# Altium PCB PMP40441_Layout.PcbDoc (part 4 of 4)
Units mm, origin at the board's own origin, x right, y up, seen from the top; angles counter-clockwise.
Board outline 66.04 x 61.04 mm, 4 copper layers (Top Layer, Layer 2, Layer 3, Bottom Layer), stack 2.028 mm thick; 208 components, 122 nets, 788 pads, 545 vias.
Unrouted connection lines stored in the file: 24.
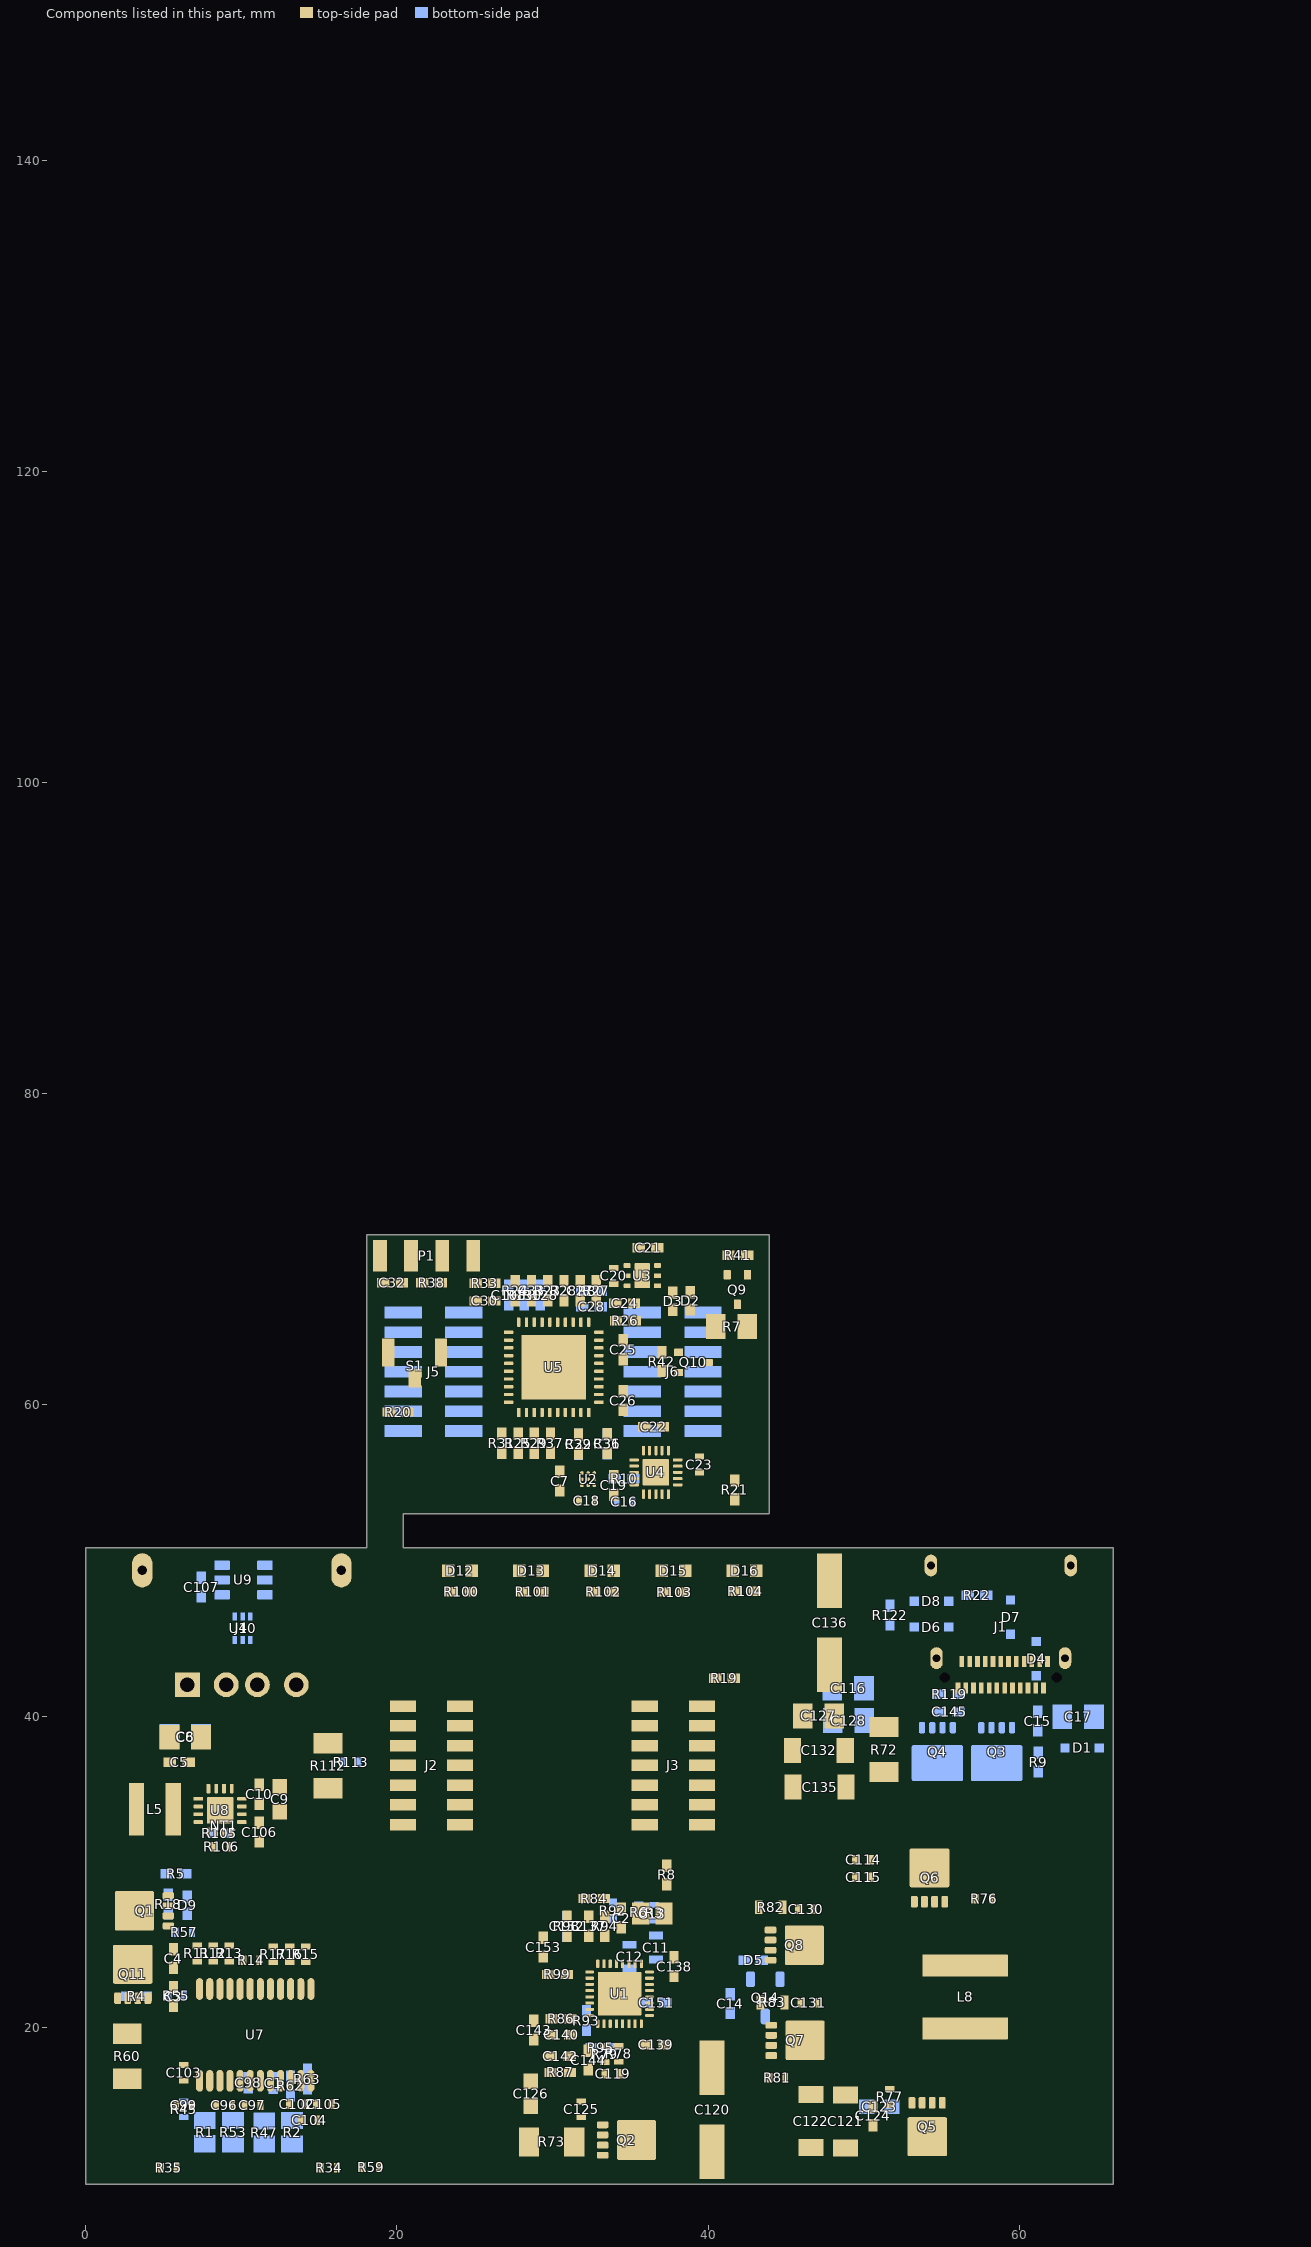
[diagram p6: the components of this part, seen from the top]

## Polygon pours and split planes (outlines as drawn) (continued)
CELL2 on Bottom Layer "Top Layer-No Net 9" (solid, remove dead copper, pour order 285): 10.947,11.379 10.719,11.151 10.719,10.719 10.871,10.566 12.275,10.566 12.3,10.566 12.453,10.719 12.453,11.201 12.275,11.379
NetR1_2 on Bottom Layer "Top Layer-No Net 9" (solid, remove dead copper, pour order 311): 13.513,11.379 13.284,11.151 13.284,10.719 13.437,10.566 14.84,10.566 14.866,10.566 15.018,10.719 15.018,11.201 14.84,11.379
CELL_N on Bottom Layer "Top Layer-No Net 9" (solid, remove dead copper, pour order 315): 6.071,11.405 5.842,11.176 5.842,10.744 5.994,10.592 7.398,10.592 7.423,10.592 7.576,10.744 7.576,11.227 7.398,11.405
VSYS on Bottom Layer "VSYS_L04_P220" (solid, remove dead copper, pour order 220): 2.565,34.468 1.295,34.468 1.092,34.265 1.092,33.934 1.321,33.706 2.591,33.706 2.769,33.884 2.769,34.265
VBAT- on Bottom Layer "Top Layer-No Net 10" (solid, remove dead copper, pour order 335): 3.327,18.034 4.877,18.034 5.105,17.805 5.105,13.437 5.105,10.82 4.496,10.211 0.838,10.211 0.279,10.77 0.279,17.678 0.635,18.034 1.905,18.034 2.134,17.805 2.134,17.526 2.337,17.323 2.616,17.323 2.87,17.323 3.023,17.475 3.023,17.729
VSYS on Bottom Layer "Bottom Layer-No Net 10" (solid, remove dead copper, pour order 269): 51.194,14.427 51.194,11.328 51.651,10.871 58.331,10.871 59.042,11.582 59.042,14.935 57.417,16.56 53.327,16.56
VSYS on Bottom Layer "Bottom Layer-No Net 11" (solid, remove dead copper, pour order 223): 41.407,13.131 41.407,10.972 41.56,10.82 41.966,10.82 42.169,11.023 42.169,13.157 42.093,13.233 41.509,13.233
VSYS on Bottom Layer "Bottom Layer-No Net 12" (solid, remove dead copper, pour order 278): 34.75,14.023 34.265,13.538 34.265,11.633 34.542,11.356 36.578,11.356 36.805,11.582 36.805,13.785 36.566,14.023
HB_SW1 on Bottom Layer "Bottom Layer-No Net 5" (solid, remove dead copper, pour order 242): 44.804,27.049 44.804,23.772 45.022,23.554 45.072,23.554 46.252,22.375 62.533,22.375 62.914,22.756 62.914,28.217 62.559,28.573 50.072,28.573 48.853,27.353 45.109,27.353
NetQ1_5 on Bottom Layer "NETQ1_5_L04_P327" (solid, remove dead copper, pour order 327): 0.965,25.273 0.965,23.443 1.472,22.936 3.734,22.936 4.278,23.481 4.278,24.652 3.658,25.273
NetQ1_5 on Bottom Layer "NETQ1_5_L04_P325" (solid, remove dead copper, pour order 325): 1.27,29.235 1.118,29.083 1.118,26.772 1.626,26.264 3.734,26.264 4.267,26.797 4.267,28.194 3.785,28.677 2.057,28.677 1.499,29.235
VO_A on Bottom Layer "VO_A_L04_P216" (solid, remove dead copper, pour order 216): 4.343,43.205 3.251,42.113 3.251,38.1 4.013,37.338 5.664,37.338 6.198,37.871 6.198,40.005 7.442,41.25 7.442,43.078 6.731,43.79 4.877,43.79
VSYS on Bottom Layer "VSYS_L04_P355" (solid, remove dead copper, pour order 355): 11.709,32.868 11.709,32.487 11.913,32.283 13.183,32.283 13.386,32.487 13.386,32.817 13.183,33.02 11.862,33.02
VBUS1 on Bottom Layer "VBUS1_L04_P363" (solid, remove dead copper, pour order 363): 52.832,38.735 55.245,38.735 55.372,38.862 55.372,41.783 55.245,41.91 54.864,41.91 53.467,43.307 49.911,43.307 49.276,42.672 49.276,38.608 49.911,37.973 52.07,37.973
VSBUS on Bottom Layer "VSBUS_L04_P365" (solid, remove dead copper, pour order 365): 60.198,38.1 60.452,37.846 60.452,35.941 60.325,35.814 53.086,35.814 52.832,36.068 52.832,37.846 53.086,38.1
CHG_ACN on Bottom Layer "CHG_ACN_L04_P377" (solid, remove dead copper, pour order 377): 50.546,37.592 52.451,37.592 52.578,37.465 52.578,35.814 52.832,35.56 62.865,35.56 63.246,35.179 63.246,29.464 62.738,28.956 50.292,28.956 50.038,29.21 50.165,29.337 50.165,37.211
VBUS on Bottom Layer "VBUS_L04_P379" (solid, remove dead copper, pour order 379): 57.531,38.735 59.055,38.735 59.182,38.862 59.182,39.624 59.309,39.751 61.468,39.751 61.976,39.243 61.976,37.846 62.357,37.465 63.627,37.465 63.881,37.719 63.881,40.64 63.119,41.402 57.404,41.402 57.15,41.148 57.15,39.116
PGND on Bottom Layer "PGND_L04_P391" (solid, remove dead copper, pour order 391): 1.524,50.546 64.77,50.546 65.913,49.403 65.913,10.668 65.405,10.16 0.762,10.16 0.254,10.668 0.254,49.276
NetC3_2 on Layer 2 "NETC3_2_L02_P345" (solid, remove dead copper, pour order 345): 0.61,21.666 0.279,21.336 0.279,19.38 0.483,19.177 0.94,19.177 1.118,19.355 1.118,21.463 0.914,21.666
AGND on Layer 2 "AGND_L02_P339" (solid, remove dead copper, pour order 339): 19.101,70.764 18.339,70.002 18.339,54.585 19.456,53.467 42.748,53.467 43.536,54.254 43.536,70.282 43.053,70.764
no net on Layer 2 "Top Layer-No Net 7" (solid, remove dead copper, shelved, pour order 291): 24.968,15.152 24.968,10.77 25.502,10.236 30.124,10.236 30.328,10.439 30.328,11.938 30.124,12.141 29.921,12.141 29.769,12.294 29.769,13.056 29.896,13.183 30.15,13.183 30.328,13.36 30.328,14.554 29.413,15.469 25.285,15.469
HB_SW1 on Layer 2 "Bottom Layer-No Net 5" (solid, remove dead copper, pour order 247): 44.754,27.026 44.754,23.749 44.972,23.531 45.023,23.531 46.202,22.352 62.483,22.352 62.864,22.733 62.864,28.194 62.509,28.55 50.022,28.55 48.803,27.33 45.059,27.33
VSYS on Layer 2 "Bottom Layer-No Net 10" (solid, remove dead copper, pour order 273): 52.092,13.839 52.092,11.354 52.727,10.719 57.705,10.719 58.113,11.126 58.113,13.973 57.887,14.199 52.451,14.199
VSYS on Layer 2 "Bottom Layer-No Net 12" (solid, remove dead copper, pour order 293): 34.788,14.131 34.23,13.572 34.23,11.895 34.661,11.464 36.203,11.464 36.627,11.887 36.627,13.614 36.111,14.131
VSYS on Layer 2 "Bottom Layer-No Net 11" (solid, remove dead copper, pour order 222): 41.377,13.132 41.377,10.973 41.529,10.82 41.935,10.82 42.139,11.024 42.139,13.157 42.062,13.233 41.478,13.233
VBAT+ on Layer 2 "VBAT+_L02_P295" (solid, remove dead copper, pour order 295): 23.571,14.376 22.911,13.716 22.911,11.608 23.343,11.176 29.439,11.176 29.693,11.43 29.693,11.824 29.439,12.078 29.286,12.078 29.134,12.23 29.134,13.043 29.261,13.17 29.515,13.17 29.693,13.348 29.693,13.945 29.261,14.376
VBAT- on Layer 2 "Top Layer-No Net 10" (solid, remove dead copper, pour order 299): 3.251,18.034 4.877,18.034 5.105,17.805 5.105,13.437 5.105,10.795 4.521,10.211 0.838,10.211 0.279,10.77 0.279,17.678 0.635,18.034 1.905,18.034 2.134,17.805 2.134,17.526 2.337,17.323 2.616,17.323 2.87,17.323 3.023,17.475 3.023,17.805
NetQ1_5 on Layer 2 "NETQ1_5_L02_P319" (solid, remove dead copper, pour order 319): 1.321,29.21 0.94,28.829 0.94,23.546 1.6,22.885 3.835,22.885 4.394,23.444 4.394,28.194 3.378,29.21
VSYS on Layer 2 "VSYS_L02_P232" (solid, remove dead copper, pour order 232): 11.913,32.283 13.183,32.283 13.386,32.487 13.386,32.817 13.157,33.045 11.887,33.045 11.709,32.868 11.709,32.487
VO_A on Layer 2 "VO_A_L02_P349" (solid, remove dead copper, pour order 349): 3.683,39.853 3.454,39.624 3.454,38.329 3.658,38.125 4.089,38.125 4.267,38.303 4.267,39.649 4.064,39.853
VBUS1 on Layer 2 "VBUS1_L02_P359" (solid, remove dead copper, pour order 359): 51.054,42.672 53.721,42.672 54.102,42.291 54.102,40.005 53.848,39.751 51.181,39.751 50.927,40.005 50.927,42.545
CHG_ACN on Layer 2 "CHG_ACN_L02_P373" (solid, remove dead copper, pour order 373): 50.546,37.592 52.451,37.592 52.578,37.465 52.578,35.814 52.832,35.56 62.865,35.56 63.246,35.179 63.246,29.464 62.738,28.956 50.292,28.956 50.038,29.21 50.165,29.337 50.165,37.211
VSBUS on Layer 2 "VSBUS_L02_P383" (solid, remove dead copper, pour order 383): 60.198,38.1 60.452,37.846 60.452,35.941 60.325,35.814 53.086,35.814 52.832,36.068 52.832,37.846 53.086,38.1
PGND on Layer 2 "PGND_L02_P387" (solid, remove dead copper, pour order 387): 1.524,50.546 64.77,50.546 65.913,49.403 65.913,10.668 65.405,10.16 0.762,10.16 0.254,10.668 0.254,49.276
NetC3_2 on Layer 3 "NETC3_2_L03_P351" (solid, remove dead copper, pour order 351): 0.61,21.666 0.279,21.336 0.279,19.38 0.483,19.177 0.94,19.177 1.118,19.355 1.118,21.463 0.914,21.666
AGND on Layer 3 "AGND_L03_P343" (solid, remove dead copper, pour order 343): 19.101,70.764 18.339,70.002 18.339,54.585 19.456,53.467 42.748,53.467 43.536,54.254 43.536,70.282 43.053,70.764
HB_SW1 on Layer 3 "Bottom Layer-No Net 5" (solid, remove dead copper, pour order 237): 44.82,26.67 44.82,23.735 45.378,23.176 46.202,22.352 62.509,22.352 62.916,22.758 62.916,28.219 62.56,28.575 60.122,28.575 59.055,27.508 54.292,27.508 53.96,27.176 53.323,26.539 52.469,26.539 52.033,26.975 45.124,26.975
VBAT+ on Layer 3 "Top Layer-No Net 7" (solid, remove dead copper, pour order 246): 24.968,14.116 24.968,10.77 25.502,10.236 29.425,10.236 29.566,10.377 29.566,10.7 28.473,11.792 28.473,14.478 28.245,14.707 26.721,14.707 25.559,14.707
VSYS on Layer 3 "Bottom Layer-No Net 12" (solid, remove dead copper, pour order 303): 34.774,14.032 34.215,13.473 34.215,11.796 34.647,11.365 35.96,11.365 36.612,12.017 36.612,13.299 35.879,14.032
VSYS on Layer 3 "Bottom Layer-No Net 11" (solid, remove dead copper, pour order 301): 41.377,13.132 41.377,10.973 41.529,10.82 41.935,10.82 42.139,11.024 42.139,13.157 42.062,13.233 41.478,13.233
VSYS on Layer 3 "Bottom Layer-No Net 10" (solid, remove dead copper, pour order 268): 52.532,13.398 52.532,10.744 53.04,10.236 56.667,10.236 58.577,12.146 58.577,14.491 58.057,15.011 54.145,15.011
VSYS on Layer 3 "VSYS_L03_P226" (solid, remove dead copper, pour order 226): 13.214,33.045 13.417,32.842 13.417,32.461 13.24,32.283 11.792,32.283 11.589,32.487 11.589,32.893 11.741,33.045
NetQ1_5 on Layer 3 "NETQ1_5_L03_P309" (solid, remove dead copper, pour order 309): 0.965,25.146 0.965,23.444 1.499,22.911 3.683,22.911 4.293,23.52 4.293,24.613 3.632,25.273 1.092,25.273
NetQ1_5 on Layer 3 "NETQ1_5_L03_P313" (solid, remove dead copper, pour order 313): 1.092,28.931 1.092,26.69 1.569,26.213 3.632,26.213 4.254,26.834 4.254,28.131 3.327,29.058 1.219,29.058
VBAT+ on Layer 3 "VBAT+_L03_P323" (solid, remove dead copper, pour order 323): 23.19,13.995 22.733,13.538 22.733,11.608 23.165,11.176 24.638,11.176 24.968,11.506 24.968,13.691 24.663,13.995
VBAT- on Layer 3 "Top Layer-No Net 10" (solid, remove dead copper, pour order 337): 3.251,18.034 4.877,18.034 5.105,17.805 5.105,13.437 5.105,10.795 4.521,10.211 0.838,10.211 0.279,10.77 0.279,17.678 0.635,18.034 1.905,18.034 2.134,17.805 2.134,17.526 2.337,17.323 2.616,17.323 2.87,17.323 3.023,17.475 3.023,17.805
VO_A on Layer 3 "VO_A_L03_P357" (solid, remove dead copper, pour order 357): 3.708,39.802 3.454,39.548 3.454,38.354 3.658,38.151 4.089,38.151 4.216,38.278 4.216,39.7 4.115,39.802
GND_A on Layer 3 "GND_A_L03_P218" (solid, remove dead copper, pour order 218): 1.473,50.571 0.33,49.428 0.33,40.691 2.438,38.583 14.656,38.583 17.475,41.402 17.475,50.063 16.942,50.597
VBUS1 on Layer 3 "VBUS1_L03_P361" (solid, remove dead copper, pour order 361): 51.054,42.672 53.721,42.672 54.102,42.291 54.102,40.005 53.848,39.751 51.181,39.751 50.927,40.005 50.927,42.545
CHG_ACN on Layer 3 "CHG_ACN_L03_P375" (solid, remove dead copper, pour order 375): 50.546,37.592 52.451,37.592 52.578,37.465 52.578,35.814 52.832,35.56 62.865,35.56 63.246,35.179 63.246,29.464 62.738,28.956 50.292,28.956 50.038,29.21 50.165,29.337 50.165,37.211
VSBUS on Layer 3 "VSBUS_L03_P385" (solid, remove dead copper, pour order 385): 60.198,38.1 60.452,37.846 60.452,35.941 60.325,35.814 53.086,35.814 52.832,36.068 52.832,37.846 53.086,38.1
PGND on Layer 3 "PGND_L03_P389" (solid, remove dead copper, pour order 389): 1.524,50.546 64.77,50.546 65.913,49.403 65.913,10.668 65.405,10.16 0.762,10.16 0.254,10.668 0.254,49.276

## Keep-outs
Keep-Out Layer:
  lines w0.025: 66.04,10.922 66.04,51.816 ; 66.04,11.938 66.04,52.832 ; 0,9.906 66.04,9.906 66.04,50.8 20.396,50.8 20.396,53.01 43.942,53.01 43.942,70.942 18.059,70.942 18.059,50.8 0,50.8 0,9.906
  text ".Layer_Name" at 14.656,-21.806 h1.52

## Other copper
Top Layer:
  pour cut-out: 28.397,19.736 28.245,19.583 28.245,18.821 28.397,18.669 29.058,18.669 29.261,18.466 29.261,16.764 29.435,16.59 30.832,16.59 31.953,16.59 31.953,19.126 31.344,19.736
  pour cut-out: 29.159,25.146 28.931,24.917 28.931,23.266 29.286,22.911 30.226,22.911 30.531,23.216 30.531,24.613 29.997,25.146
  pour cut-out: 30.505,27.594 30.505,26.746 30.836,26.416 36.22,26.416 36.424,26.619 36.424,28.067 36.22,28.27 31.182,28.27
  text ".Layer_Name" at 14.656,-21.806 h1.52
Layer 2:
  pour cut-out: 29.591,19.05 29.591,18.694 29.743,18.542 30.15,18.542 30.302,18.694 30.302,19.05 30.124,19.228 29.769,19.228
  pour cut-out: 32.664,27.051 32.791,26.924 32.791,25.222 32.283,24.714 29.972,24.714 29.82,24.562 29.82,24.232 29.972,24.079 31.801,24.079 32.156,23.724 32.156,21.514 29.859,19.217 30.161,18.706 32.106,20.65 33.401,20.65 33.604,20.853 33.604,21.302 32.859,22.047 32.859,24.299 33.528,24.968 33.528,27.051 35.052,27.051 35.179,27.178 35.179,27.508 35.052,27.635 31.42,27.635 31.318,27.534 31.318,27.153 31.42,27.051
Layer 3:
  pour cut-out: 29.743,19.202 29.604,19.063 29.604,18.682 29.794,18.491 30.124,18.491 30.302,18.669 30.302,19.05 30.15,19.202
  pour cut-out: 29.997,24.765 29.858,24.625 29.858,24.244 30.048,24.054 30.378,24.054 30.556,24.232 30.556,24.613 30.404,24.765
  pour cut-out: 31.42,27.635 31.318,27.534 31.318,27.153 31.394,27.076 31.775,27.076 31.877,27.178 31.877,27.508 31.75,27.635
  pour cut-out: 34.696,27.635 34.595,27.534 34.595,27.153 34.671,27.076 35.052,27.076 35.154,27.178 35.154,27.508 35.027,27.635
  pour cut-out: 32.969,21.361 32.829,21.222 32.83,20.841 33.02,20.65 33.35,20.65 33.528,20.828 33.528,21.209 33.376,21.361
Bottom Layer:
  pour cut-out: 32.639,21.082 32.639,19.736 34.036,19.736 34.036,20.65 33.325,21.361 32.918,21.361
  pour cut-out: 33.35,19.075 33.172,18.898 33.172,18.339 33.325,18.186 34.138,18.186 34.29,18.339 34.29,18.948 34.162,19.076
  pour cut-out: 29.591,19.05 29.591,18.694 29.743,18.542 30.15,18.542 30.302,18.694 30.302,19.05 30.124,19.228 29.769,19.228
  pour cut-out: 29.997,24.765 29.858,24.625 29.858,24.244 30.048,24.054 30.378,24.054 30.556,24.232 30.556,24.613 30.404,24.765
  pour cut-out: 30.48,27.534 30.48,26.619 30.531,26.568 31.318,26.568 31.928,27.178 31.928,27.508 31.801,27.635 30.582,27.635
  pour cut-out: 34.696,27.635 34.595,27.534 34.595,27.153 34.671,27.076 35.052,27.076 35.154,27.178 35.154,27.508 35.027,27.635
  pour cut-out: 36.88,25.757 37.313,25.324 37.313,24.079 36.678,23.444 34.493,23.444 34.341,23.597 34.341,25.453 34.645,25.757
  text ".Layer_Name" at 14.656,-21.806 h1.52

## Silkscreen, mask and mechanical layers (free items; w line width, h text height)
Top Overlay:
  text "PMP40441" at 16.993,28.829 h1.52
  text "Rev.1.1" at 16.993,26.873 h1.02
  text "-" at 3.835,13.843 h1.52
  text "+" at 20.625,13.741 h1.52
  text "3" at 14.453,11.633 h0.76
  text "0" at 7.137,11.608 h0.76
  text "1" at 9.703,11.608 h0.76
  text "2" at 11.963,11.608 h0.76
  text ".Layer_Name" at 14.656,-21.806 h1.52
Bottom Overlay:
  text "PMP40442" at 27.229,55.093 h1.85
  text ".Layer_Name" at 14.656,-21.806 h1.52
Top Paste:
  region: 47.669,27.28 47.669,22.733 52.153,22.733 52.153,27.28
  text ".Layer_Name" at 14.656,-21.806 h1.52
Bottom Paste:
  text ".Layer_Name" at 14.656,-21.806 h1.52
Top Solder:
  region: 13.494,11.379 13.316,11.201 13.316,10.719 13.469,10.566 14.808,10.566 14.808,11.379
  region: 10.954,11.379 10.776,11.201 10.776,10.719 10.929,10.566 12.294,10.566 12.471,10.744 12.471,11.201 12.294,11.379
  region: 8.541,11.405 8.363,11.227 8.363,10.744 8.516,10.592 9.881,10.592 10.058,10.77 10.058,11.227 9.881,11.405
  region: 47.663,27.292 47.663,22.746 52.146,22.746 52.146,27.292
  region: 0.279,13.97 0.279,10.77 0.813,10.236 4.394,10.236 4.394,11.506 5.08,11.506 5.08,12.497 5.08,13.97
  region: 6.198,11.405 6.198,10.592 7.391,10.592 7.569,10.77 7.569,11.227 7.391,11.405
  region: 22.022,15.189 22.022,10.262 26.365,10.262 26.365,15.189
  region: 50.673,34.925 62.738,34.925 63.246,34.417 63.246,29.464 62.738,28.956 50.546,28.956 50.165,29.337 50.165,34.417
  text ".Layer_Name" at 14.656,-21.806 h1.52
  text ".Layer_Name" at 14.656,-21.806 h1.52
Bottom Solder:
  region: 5.055,17.069 0.33,17.069 0.33,10.719 0.762,10.287 4.521,10.287 5.055,10.82
  region: 36.779,13.679 36.779,11.569 36.581,11.371 34.527,11.371 34.239,11.659 34.239,13.487 34.79,14.038 36.551,14.038 36.779,13.809
  region: 35.23,20.632 35.23,23.292 32.842,23.292 32.842,21.946 34.156,20.632
  region: 58.177,28.393 59.117,27.454 59.752,27.454 60.59,28.292 62.724,28.292 62.724,22.602 46.283,22.602 44.969,23.915 44.969,27.123 45.227,27.381 48.971,27.381 49.983,28.393 52.696,28.393
  region: 59.03,14.91 59.03,11.659 58.268,10.897 51.74,10.897 51.232,11.405 51.232,13.97 52.756,13.97 52.756,14.681 54.61,16.535 57.404,16.535
  region: 50.673,34.925 62.738,34.925 63.246,34.417 63.246,29.464 62.738,28.956 50.546,28.956 50.165,29.337 50.165,34.417
  text ".Layer_Name" at 14.656,-21.806 h1.52
Drill Guide:
  text ".Layer_Name" at 14.656,-21.806 h1.52
M1 Board Outline:
  the board outline again, w0.051
  text ".Layer_Name" at 14.656,-21.806 h1.52
M2 Board Dimensions:
  rectangle: 3.175,-10.16 12.7,-6.985
  rectangle: 0,-6.985 3.175,-3.81
  lines w0.178: 0,-6.985 25.4,-6.985 ; 3.175,-10.16 3.175,-3.81 ; 6.35,-10.16 6.35,-3.81 ; 12.7,-10.16 12.7,-3.81 ; 19.05,-10.16 19.05,-3.81 ; 0,-10.16 0,-3.81 25.4,-3.81 25.4,-10.16 0,-10.16
  text ".Layer_Name" at 14.656,-21.806 h1.52
M3 3D STEP Top:
  text ".Layer_Name" at 14.656,-21.806 h1.52
M4 3D STEP Bottom:
  text ".Layer_Name" at 14.656,-21.806 h1.52
M5 Assembly Top:
  lines w0.254: -7.417,-23.626 160.223,-23.626 ; -7.417,-18.462 160.274,-18.462 ; -7.417,-13.297 -7.417,-28.791 94.31,-28.791 160.274,-28.791 160.274,-13.297 -7.404,-13.297 -7.404,-28.791 32.614,-28.791 ; 55.194,-28.791 55.194,-13.297 ; 87.376,-18.462 87.376,-13.297 ; 108.712,-18.462 108.712,-13.297 ; 124.511,-28.956 124.511,-23.804
  text "COMPONENTS MARKED 'DNP' SHOULD NOT BE POPULATED." at 29.299,-8.09 h1.52
  text "ASSEMBLY VARIANT:" at 29.286,-11.024 h1.52
  text ".VariantName" at 55.601,-11.024 h1.52
  text "PCB VIEWED FROM TOP SIDE" at -5.804,-16.654 h1.52
  text "BOARD #:" at 57.099,-16.654 h1.52
  text ".PRJ_Number" at 70.955,-16.654 h1.52
  text "REV:" at 92.405,-16.654 h1.52
  text ".PCB_Rev" at 99.809,-16.654 h1.52
  text "SVN REV:" at 113.69,-16.654 h1.52
  text ".VersionControl_RevNumber" at 126.543,-16.654 h1.52
  text "TID #:" at 57.099,-21.819 h1.52
  text ".TID" at 70.955,-21.819 h1.52
  text "PLOT NAME =" at -5.804,-27.034 h1.52
  text ".plot_File_Name" at 14.656,-27.034 h1.52
  text "GENERATED    :" at 57.15,-27.034 h1.52
  text ".Print_Date" at 79.235,-27.034 h1.52
  text ".Print_Time" at 97.752,-27.034 h1.52
  text "TEXAS INSTRUMENTS" at 129.87,-27.034 h1.52
M6 Assembly Bottom:
  lines w0.254: -7.429,-18.474 160.261,-18.474 ; -7.379,-23.639 160.261,-23.639 ; 28.334,-28.969 28.334,-23.817 ; 44.133,-18.474 44.133,-13.31 ; 65.468,-18.474 65.468,-13.31 ; 97.65,-28.804 97.65,-13.31 ; 120.231,-28.804 160.249,-28.804 160.249,-13.31 -7.429,-13.31 -7.429,-28.804 58.534,-28.804 160.261,-28.804 160.261,-13.31
  text "COMPONENTS MARKED 'DNP' SHOULD NOT BE POPULATED." at 154.991,-8.077 h1.52
  text ".VariantName" at 128.473,-11.024 h1.52
  text "ASSEMBLY VARIANT:" at 154.864,-11.024 h1.52
  text ".VersionControl_RevNumber" at 26.302,-16.667 h1.52
  text "SVN REV:" at 39.154,-16.667 h1.52
  text ".PCB_Rev" at 53.035,-16.667 h1.52
  text "REV:" at 60.439,-16.667 h1.52
  text ".PRJ_Number" at 81.89,-16.667 h1.52
  text "BOARD #:" at 95.745,-16.667 h1.52
  text "PCB VIEWED FROM BOTTOM SIDE" at 158.648,-16.667 h1.52
  text ".TID" at 81.89,-21.831 h1.52
  text "TID #:" at 95.745,-21.831 h1.52
  text "TEXAS INSTRUMENTS" at 22.974,-27.047 h1.52
  text ".Print_Time" at 55.093,-27.047 h1.52
  text ".Print_Date" at 73.609,-27.047 h1.52
  text "GENERATED    :" at 95.694,-27.047 h1.52
  text ".plot_File_Name" at 138.189,-27.047 h1.52
  text "PLOT NAME =" at 158.648,-27.047 h1.52
M9 Title Sheet:
  drawing of 57 lines, arcs and shapes, not listed
  text "1" at 18.792,204.127 h1.78
  text "2" at 82.182,204.127 h1.78
  text "3" at 145.411,204.127 h1.78
  text "4" at 209.08,204.127 h1.78
  text "5" at 272.555,204.127 h1.78
  text "6" at 336.182,204.127 h1.78
  text "A" at -10.579,175.095 h1.78
  text "A" at 365.341,175.095 h1.78
  text "B" at -10.579,114.643 h1.78
  text "B" at 365.341,114.643 h1.78
  text "C" at -10.579,54.318 h1.78
  text "C" at 365.341,54.318 h1.78
  text "PROJECT TITLE:" at 288.125,7.048 h1.14
  text ".PRJ_Title" at 289.395,3.662 h1.78
  text "DESIGNED FOR:" at 288.125,-0.597 h1.14
  text ".PRJ_Customer" at 289.395,-4.153 h1.78
  text "D" at -10.579,-5.88 h1.78
  text "D" at 365.341,-5.88 h1.78
  text "FILE NAME:" at 288.125,-8.217 h1.14
  text ".PCB_File_Name_No_Path" at 289.395,-11.265 h1.78
  text "Texas Instruments (TI) and/or its licensors do not warrant the accuracy or completeness of this specification" at 161.9,-15.376 h1.14
  text "ENGINEER:" at 288.125,-15.583 h1.14
  text "LAYOUT BY:" at 326.352,-15.583 h1.14
  text "or any information contained therein. TI and/or its licensors do not warrant that this design will meet" at 160.757,-18.237 h1.14
  text ".PRJ_Engineer" at 289.395,-19.52 h1.78
  text ".PCB_Layout" at 327.635,-19.52 h1.78
  text "the specifications, will be suitable for your application or fit for any particular purpose, or will operate in" at 160.757,-21.099 h1.14
  text ".Layer_Name" at 14.656,-21.806 h1.52
  text "ALTIUM DESIGNER VERSION:" at 326.352,-23.457 h1.14
  text "an implementation. TI and/or its licensors do not warrant that the design is production worthy. You should" at 160.757,-23.961 h1.14
  text "completely validate and test your design implementation to confirm the system functionality for your application." at 161.9,-26.822 h1.14
  text ".print_Scale" at 289.395,-26.843 h1.78
  text ".Application_BuildNumber" at 327.635,-26.843 h1.78
  text "1" at 18.792,-32.093 h1.78
  text "2" at 82.182,-32.093 h1.78
  text "3" at 145.411,-32.093 h1.78
  text "4" at 209.08,-32.093 h1.78
  text "5" at 272.555,-32.093 h1.78
  text "6" at 336.182,-32.093 h1.78
M10 Fab Notes:
  drawing of 173 lines, arcs and shapes, not listed
  text "DESIGN INFORMATION" at 314.376,157.505 h1.52
  text "MIN. TRACK WIDTH:" at 298.004,152.933 h1.52
  text "8" at 325.849,152.933 h1.52
  text "MIL" at 329.78,152.933 h1.52
  text "MIN. CLEARANCE:" at 298.004,149.581 h1.52
  text "0.2" at 324.325,149.581 h1.52
  text "mm" at 329.78,149.581 h1.52
  text "MIN. VIA PAD SIZE:" at 298.004,146.228 h1.52
  text "24" at 325.087,146.228 h1.52
  text "MIL" at 329.78,146.228 h1.52
  text "0.05mm (2MIL)" at 315.657,142.628 h1.52
  text "MINIMUM ANNULAR RING" at 289.642,142.52 h1.52
  text "EXTERNAL" at 333.641,142.52 h1.52
  text "PER" at 294.722,139.522 h1.52
  text "IPC-D-275 CLASS 2 LEVEL C" at 300.31,139.522 h1.52
  text "MIL, HOLES" at 338.111,136.67 h1.52
  text "+/-" at 328.143,136.652 h1.52
  text "+/-" at 349.834,136.652 h1.52
  text "REGISTRATION TOLERANCES:" at 289.642,136.525 h1.52
  text "METAL" at 320.116,136.525 h1.52
  text "5" at 334.752,136.525 h1.52
  text "3" at 355.91,136.525 h1.52
  text "MIL" at 358.863,136.525 h1.52
  text "+/-" at 349.834,133.655 h1.52
  text "HOLE SIZE TOLERANCE (UNLESS OTHERWISE SPECIFIED):" at 289.642,133.528 h1.52
  text "3" at 355.91,133.528 h1.52
  text "MIL" at 358.863,133.528 h1.52
  text "MATERIAL:" at 287.743,128.208 h1.52
  text "FR-4 High Tg" at 312.799,124.643 h1.52
  text "FR-408" at 298.436,124.425 h1.52
  text "OTHER" at 336.231,124.425 h1.52
  text "X" at 308.864,124.333 h1.52
  text "62 MIL (1.6mm) +/-10%" at 306.567,120.292 h1.52
  text "THICKNESS:" at 289.642,120.184 h1.52
  text "X" at 303.311,120.184 h1.52
  text "OTHER" at 339.203,120.184 h1.52
  text "TOLERANCE:" at 289.642,116.17 h1.52
  text "X" at 310.96,116.17 h1.52
  text "ANSI IPC-6012 TYPE 3 CLASS 2" at 315.709,116.17 h1.52
  text "OTHER +/-" at 315.708,112.208 h1.52
  text "BOW & TWIST:" at 289.642,108.22 h1.52
  text "X" at 310.96,108.22 h1.52
  text "ANSI IPC-6012 TYPE 3 CLASS 2" at 315.709,108.22 h1.52
  text "OTHER +/-" at 315.708,104.194 h1.52
  text "DRILLING:" at 287.743,100.676 h1.52
  text "REFERENCE:" at 289.642,97.705 h1.52
  text "X" at 306.107,97.705 h1.52
  text "AS SHOWN" at 310.857,97.705 h1.52
  text "X" at 328.992,97.705 h1.52
  text "NC_DRILL FILES" at 332.472,97.705 h1.52
  text "PTH COPPER THICKNESS:" at 289.642,93.691 h1.52
  text "X" at 318.35,93.691 h1.52
  text "20-30 um" at 321.83,93.691 h1.52
  text "OTHER" at 340.041,93.691 h1.52
  text "BOARD FINISH:" at 287.743,89.653 h1.52
  text "SILKSCREEN:" at 291.685,86.656 h1.52
  text "X" at 315.784,86.656 h1.52
  text "TOP" at 318.985,86.656 h1.52
  text "X" at 328.738,86.656 h1.52
  text "BOTTOM" at 331.964,86.656 h1.52
  text "SILKSCREEN COLOR:" at 291.685,82.414 h1.52
  text "X" at 315.758,82.414 h1.52
  text "WHITE" at 318.985,82.414 h1.52
  text "OTHER" at 331.964,82.414 h1.52
  text "X" at 319.086,78.37 h1.52
  text "GREEN" at 322.312,78.37 h1.52
  text "OTHER" at 338.009,78.37 h1.52
  text "SOLDER RESIST COLOR:" at 291.685,78.096 h1.52
  text "X" at 319.086,74.052 h1.52
  text "MATTE" at 322.312,74.052 h1.52
  text "SEMI-GLOSS" at 337.998,74.036 h1.52
  text "IMMERSION GOLD (ENIG)" at 314.692,69.264 h1.52
  text "ENEPIG" at 348.666,69.18 h1.52
  text "SURFACE FINISH:" at 287.743,69.155 h1.52
  text "X" at 309.944,69.155 h1.52
  text "IMM. TIN/SILVER OR EQUIV" at 296.113,65.167 h1.52
  text "OTHER" at 332.472,65.167 h1.52
  text "ARRAY/PANEL:" at 287.743,60.621 h1.52
  text "CUT AND TRIM PER M1 BOARD OUTLINE" at 314.692,60.512 h1.52
  text "N.C. ROUTE" at 314.692,56.658 h1.52
  text "X" at 331.939,56.658 h1.52
  text "V. SCORE" at 336.689,56.658 h1.52
  text "CERTIFICATION:" at 287.743,53.178 h1.52
  text "MATERIALS AND WORKMANSHIP FOR ALL PCBS" at 306.158,53.178 h1.52
  text "TO MEET OR EXCEED THE REQUIREMENTS OF:" at 306.158,50.689 h1.52
  text "X" at 296.671,47.222 h1.52
  text "ANSI IPC-A-600F CLASS ->" at 300.202,47.222 h1.52
  text "X" at 341.834,47.222 h1.52
  text "2" at 344.855,47.222 h1.52
  text "1" at 336.854,47.184 h1.52
  text "3" at 353.846,47.184 h1.52
  text "X" at 317.348,43.171 h1.52
  text "RoHS" at 320.826,43.171 h1.52
  text "OTHER" at 337.194,43.171 h1.52
  text "PER ORDER" at 347.28,43.171 h1.52
  text "ALL BOARDS MUST MEET OR EXCEED UL94-V0 REQUIREMENTS." at 288.442,38.964 h1.52
  text "PCB MUST BEAR THE UL94V-0 UL REGISTERED MATERIAL ID NUMBER" at 288.442,35.916 h1.52
  text "ADDITIONAL REQUIREMENTS:" at 287.743,31.512 h1.52
  text "MICROSECTION:" at 289.642,28.591 h1.52
  text "YES" at 312.648,28.591 h1.52
  text "REQUIRED" at 334.53,24.625 h1.52
  text "BARE BOARD ELEC. TEST:" at 289.642,24.553 h1.52
  text "NONE" at 322.808,24.553 h1.52
  text "X" at 331.304,24.553 h1.52
  text "PER ORDER" at 349.566,24.553 h1.52
  text ".Layer_Name" at 14.656,-21.806 h1.52
M11 Gerber Information:
  lines w0.254: -7.417,-23.626 160.223,-23.626 ; -7.417,-18.462 160.274,-18.462 ; -7.417,-13.297 -7.417,-28.791 94.31,-28.791 160.274,-28.791 160.274,-13.297 -7.404,-13.297 -7.404,-28.791 32.614,-28.791 ; 55.194,-28.791 55.194,-13.297 ; 87.376,-18.462 87.376,-13.297 ; 108.712,-18.462 108.712,-13.297 ; 124.511,-28.956 124.511,-23.804
  text "ALL ARTWORK VIEWED FROM TOP SIDE" at -5.804,-16.654 h1.52
  text "BOARD #:" at 57.099,-16.654 h1.52
  text ".PRJ_Number" at 70.955,-16.654 h1.52
  text "REV:" at 92.405,-16.654 h1.52
  text ".PCB_Rev" at 99.809,-16.654 h1.52
  text "SVN REV:" at 113.69,-16.654 h1.52
  text ".VersionControl_RevNumber" at 126.543,-16.654 h1.52
  text "LAYER NAME =" at -5.804,-21.806 h1.52
  text "TID #:" at 57.099,-21.819 h1.52
  text ".TID" at 70.955,-21.819 h1.52
  text "PLOT NAME =" at -5.804,-27.034 h1.52
  text ".plot_File_Name" at 14.656,-27.034 h1.52
  text "GENERATED    :" at 57.15,-27.034 h1.52
  text ".Print_Date" at 79.235,-27.034 h1.52
  text ".Print_Time" at 97.752,-27.034 h1.52
  text "TEXAS INSTRUMENTS" at 129.87,-27.034 h1.52
M12 Stackup:
  drawing of 295 lines, arcs and shapes, not listed
  text "Layer" at 248.871,198.882 h1.52
  text "Name" at 259.283,198.882 h1.52
  text "Material" at 282.898,198.882 h1.52
  text "Thickness" at 304.736,198.882 h1.52
  text "Constant" at 321.242,198.882 h1.52
  text "Board Layer Stack" at 335.717,198.882 h1.52
  text "1" at 248.871,195.834 h1.52
  text "Top Overlay" at 259.283,195.834 h1.52
  text "2" at 248.871,192.786 h1.52
  text "Top Solder" at 259.283,192.786 h1.52
  text "Solder Resist" at 282.898,192.786 h1.52
  text "0.40mil" at 304.736,192.786 h1.52
  text "3.5" at 321.242,192.786 h1.52
  text "3" at 248.871,189.738 h1.52
  text "Top Layer" at 259.283,189.738 h1.52
  text "Copper" at 282.898,189.738 h1.52
  text "1.40mil" at 304.736,189.738 h1.52
  text "4" at 248.871,186.69 h1.52
  text "Dielectric1" at 259.283,186.69 h1.52
  text "FR-4" at 282.898,186.69 h1.52
  text "59.20mil" at 304.736,186.69 h1.52
  text "4.8" at 321.242,186.69 h1.52
  text "5" at 248.871,183.642 h1.52
  text "Layer 2" at 259.283,183.642 h1.52
  text "Copper" at 282.898,183.642 h1.52
  text "1.42mil" at 304.736,183.642 h1.52
  text "6" at 248.871,180.594 h1.52
  text "Dielectric 3" at 259.283,180.594 h1.52
  text "5.00mil" at 304.736,180.594 h1.52
  text "4.2" at 321.242,180.594 h1.52
  text "7" at 248.871,177.546 h1.52
  text "Layer 3" at 259.283,177.546 h1.52
  text "Copper" at 282.898,177.546 h1.52
  text "1.42mil" at 304.736,177.546 h1.52
  text "8" at 248.871,174.498 h1.52
  text "Dielectric 2" at 259.283,174.498 h1.52
  text "10.00mil" at 304.736,174.498 h1.52
  text "4.2" at 321.242,174.498 h1.52
  text "9" at 248.871,171.45 h1.52
  text "Bottom Layer" at 259.283,171.45 h1.52
  text "Copper" at 282.898,171.45 h1.52
  text "1.40mil" at 304.736,171.45 h1.52
  text "10" at 248.871,168.402 h1.52
  text "Bottom Solder" at 259.283,168.402 h1.52
  text "Solder Resist" at 282.898,168.402 h1.52
  text "0.40mil" at 304.736,168.402 h1.52
  text "3.5" at 321.242,168.402 h1.52
  text "11" at 248.871,165.354 h1.52
  text "Bottom Overlay" at 259.283,165.354 h1.52
  text ".Layer_Name" at 14.656,-21.806 h1.52
M13 Component Bodies Top:
  text ".Layer_Name" at 14.656,-21.806 h1.52
M14 Component Bodies Bottom:
  text ".Layer_Name" at 14.656,-21.806 h1.52
M15 Courtyards Top:
  text ".Layer_Name" at 14.656,-21.806 h1.52
M16 Courtyards Bottom:
  text ".Layer_Name" at 14.656,-21.806 h1.52
Drill Drawing:
  circle w0.254: c140.938,81.512 r0.561
  lines w0.254: 140.377,58.241 140.938,58.521 141.499,58.241 141.218,58.802 141.499,59.362 140.938,59.082 140.377,59.362 140.657,58.802 140.377,58.241 ; 140.377,60.764 141.499,60.764 141.499,61.886 140.377,61.886 140.377,60.764 ; 140.377,63.288 140.377,63.568 140.657,63.848 140.377,64.129 140.377,64.409 140.657,64.409 140.938,64.129 141.218,64.409 141.499,64.409 141.499,64.129 141.218,63.848 141.499,63.568 141.499,63.288 141.218,63.288 140.938,63.568 140.657,63.288 140.377,63.288 ; 140.377,66.091 140.657,66.091 140.657,65.811 141.218,65.811 141.218,66.091 141.499,66.091 141.499,66.652 141.218,66.652 141.218,66.932 140.657,66.932 140.657,66.652 140.377,66.652 140.377,66.091 ; 140.377,78.708 140.657,78.708 140.938,78.428 141.218,78.708 141.499,78.708 141.218,78.989 141.499,79.269 141.218,79.269 140.938,79.549 140.657,79.269 140.377,79.269 140.657,78.989 140.377,78.708 ; 140.377,84.596 141.499,84.596 140.938,83.475 140.377,84.596
  lines w0.305: 139.344,57.484 187.274,57.484 ; 139.344,85.241 187.274,85.241 ; 147.35,54.961 147.35,87.764 ; 155.399,54.961 155.399,87.764 ; 171.176,54.961 171.176,87.764 ; 177.374,54.961 177.374,87.764 ; 139.344,54.961 187.274,54.961 187.274,87.764 139.344,87.764 139.344,54.961
  text "Symbol" at 140.858,85.998 h1.83
  text "Quantity" at 148.107,85.998 h1.83
  text "Finished Hole Size" at 156.156,85.998 h1.83
  text "Plated" at 171.933,85.998 h1.83
  text "Hole Type" at 178.131,85.998 h1.83
  text "1" at 148.107,83.475 h1.52
  text "25.59mil (0.650mm)" at 156.156,83.475 h1.52
  text "NPTH" at 171.933,83.475 h1.52
  text "Round" at 178.131,83.475 h1.52
  text "1" at 148.107,80.951 h1.52
  text "25.59mil (0.650mm)" at 156.156,80.951 h1.52
  text "NPTH" at 171.933,80.951 h1.52
  text "Slot" at 178.131,80.951 h1.52
  text "1" at 148.107,78.428 h1.52
  text "6.00mil (0.152mm)" at 156.156,78.428 h1.52
  text "PTH" at 171.933,78.428 h1.52
  text "Round" at 178.131,78.428 h1.52
  text "77" at 148.107,75.904 h1.52
  text "7.87mil (0.200mm)" at 156.156,75.904 h1.52
  text "PTH" at 171.933,75.904 h1.52
  text "Round" at 178.131,75.904 h1.52
  text "I" at 140.497,75.651 h1.12
  text "228" at 148.107,73.381 h1.52
  text "8.00mil (0.203mm)" at 156.156,73.381 h1.52
  text "PTH" at 171.933,73.381 h1.52
  text "Round" at 178.131,73.381 h1.52
  text "F" at 140.31,73.127 h1.12
  text "32" at 148.107,70.858 h1.52
  text "12.00mil (0.305mm)" at 156.156,70.858 h1.52
  text "PTH" at 171.933,70.858 h1.52
  text "Round" at 178.131,70.858 h1.52
  text "H" at 140.31,70.604 h1.12
  text "205" at 148.107,68.334 h1.52
  text "16.00mil (0.406mm)" at 156.156,68.334 h1.52
  text "PTH" at 171.933,68.334 h1.52
  text "Round" at 178.131,68.334 h1.52
  text "G" at 140.31,68.081 h1.12
  text "2" at 148.107,65.811 h1.52
  text "28.00mil (0.711mm)" at 156.156,65.811 h1.52
  text "PTH" at 171.933,65.811 h1.52
  text "Round" at 178.131,65.811 h1.52
  text "4" at 148.107,63.288 h1.52
  text "37.00mil (0.940mm)" at 156.156,63.288 h1.52
  text "PTH" at 171.933,63.288 h1.52
  text "Round" at 178.131,63.288 h1.52
  text "4" at 148.107,60.764 h1.52
  text "19.69mil (0.500mm)" at 156.156,60.764 h1.52
  text "PTH" at 171.933,60.764 h1.52
  text "Slot" at 178.131,60.764 h1.52
  text "2" at 148.107,58.241 h1.52
  text "23.62mil (0.600mm)" at 156.156,58.241 h1.52
  text "PTH" at 171.933,58.241 h1.52
  text "Slot" at 178.131,58.241 h1.52
  text "557 Total" at 148.107,55.718 h1.52
  text "Slot definitions :" at 140.858,53.698 h1.52
  text "Routed Path Length" at 152.108,53.698 h1.52
  text "= Calculated from tool start centre position to tool end centre position." at 165.619,53.698 h1.52
  text "Hole Length" at 152.108,52.436 h1.52
  text "= Routed Path Length + Tool Size = Slot length as defined in the PCB layout" at 160.547,52.436 h1.52
  text ".Layer_Name" at 14.656,-21.806 h1.52

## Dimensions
0,-10.16 to 25.4,-10.16 on M2 Board Dimensions
0,9.906 to 66.04,9.906 on M2 Board Dimensions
